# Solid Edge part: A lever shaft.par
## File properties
Author: vinurabandara
Template: iso metric part.par
Last saved by: Nimesh.N
Revision: 9
Application: Solid Edge
Density: 7833.000 kg/m^3
Accuracy: 0.990
Username: Nimesh.N
Material: Steel
Face Style: Steel
Fill Style: ANSI32(Steel)
Virtual Style: Machined steel
Grouping: Metals\Steel
LibraryName: Materials
Coef. of Thermal Exp: 1.3e-05
Thermal Conductivity: 32.0
Specific Heat: 481.0
Modulus of Elasticity: 199947953000.0
Poisson's Ratio: 0.29
Yield Stress: 262000766.0
Ultimate Stress: 358527364.0
Elongation: 0.0
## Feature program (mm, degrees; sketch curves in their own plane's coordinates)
sketch for "unnamed Protrusion 1" plane through (0, 0, 0) normal (0, -1, 0) x-axis (1, 0, 0)
  circle centre (0, 0) radius 7.5
extrude "unnamed Protrusion 1" add finite 1150 along +normal
sketch for "ExtrudedProtrusion_3" plane through (0, -950, 0) normal (0, -1, 0) x-axis (1, 0, 0)
  circle centre (0, 0) radius 9.5
extrude "ExtrudedProtrusion_3" add finite 10 along +normal  Profile_Plane1_Distance = 950 mm
sketch for "ExtrudedProtrusion_4" plane through (0, -1150, 0) normal (0, -1, 0) x-axis (0, 0, -1)
extrude "ExtrudedProtrusion_4" add finite 5 along +normal
sketch for "ExtrudedProtrusion_5" plane through (0, 0, 0) normal (0, 1, 0) x-axis (-1, 0, 0)
extrude "ExtrudedProtrusion_5" add finite 5 along +normal
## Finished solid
Body 1: solid body, 7 faces, 6 edges, 0 vertices.
  Faces by surface: plane 4, cylinder 3
  Edges by curve: circle 6
Bounding box of the edges (mm): 19.000 x 1160.000 x 19.000, from (-9.5, -1155, -9.5) to (9.5, 5, 9.5).
Cylindrical faces by radius (mm): R7.5 x2, R9.5 x1
Planar faces by outward normal: +y 2, -y 2
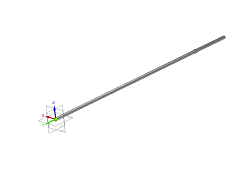
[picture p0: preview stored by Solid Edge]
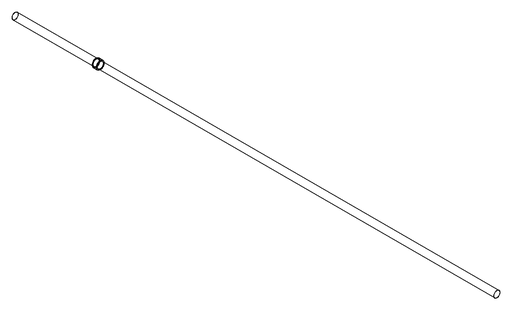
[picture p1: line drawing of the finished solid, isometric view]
